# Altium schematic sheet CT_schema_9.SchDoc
size 254 x 194 mm
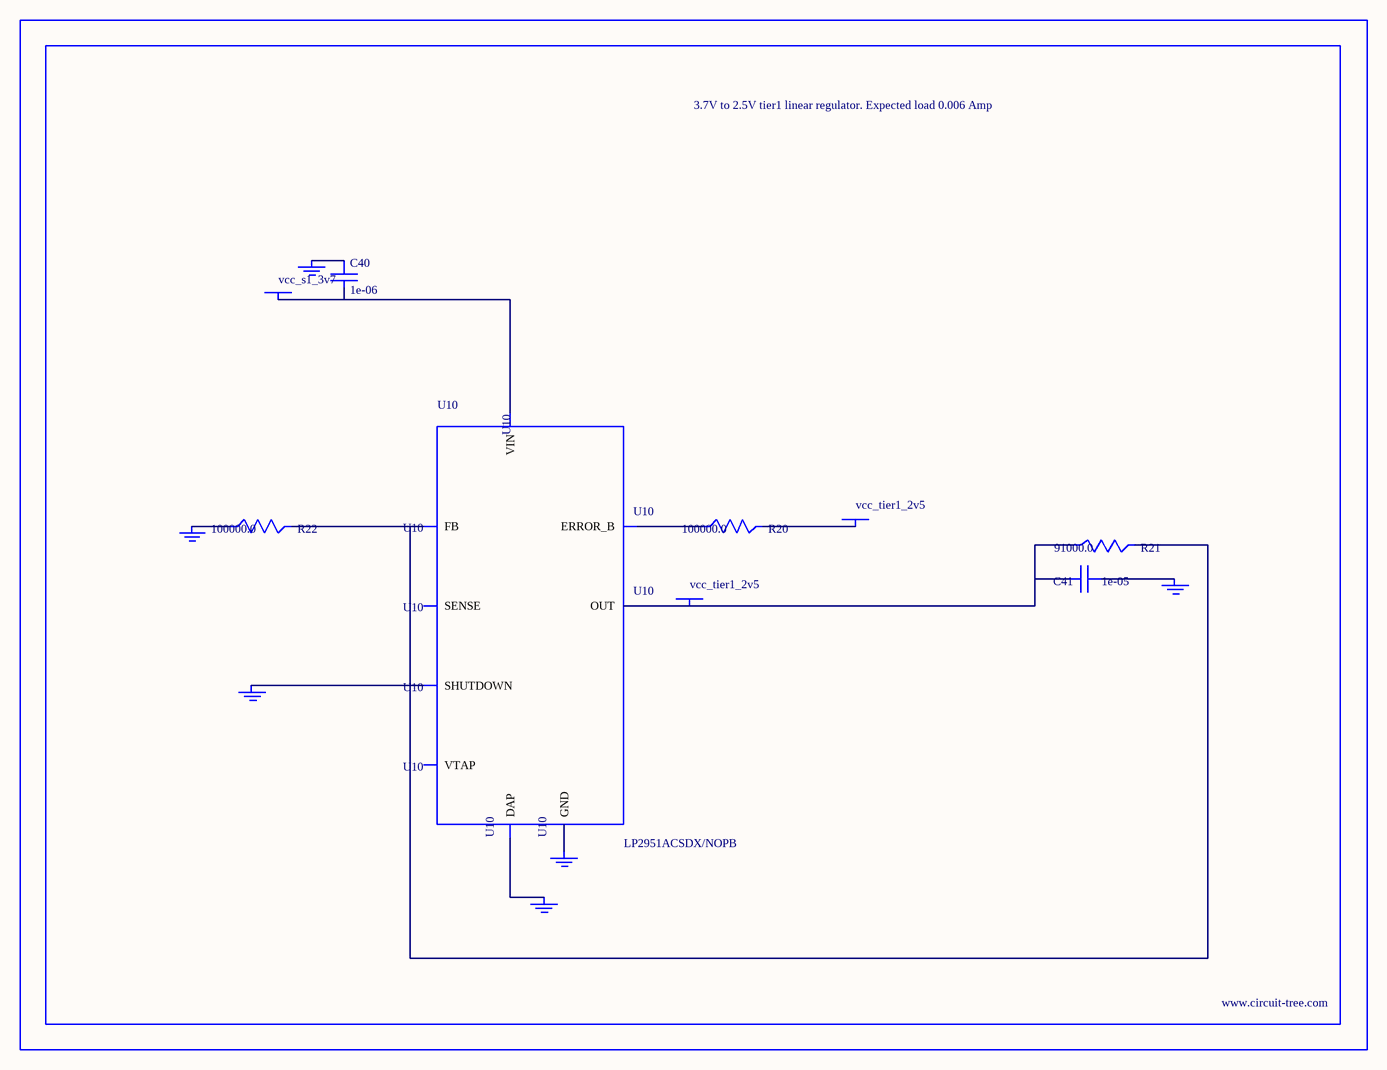
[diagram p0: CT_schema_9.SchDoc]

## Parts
BORDER8  (no value)
C40  1e-06  [C0603]
C41  1e-05  [C1210]
GND_INSTANCE_8_0  (no value)
GND_INSTANCE_8_1  (no value)
GND_INSTANCE_8_2  (no value)
GND_INSTANCE_8_3  (no value)
GND_INSTANCE_8_4  (no value)
GND_INSTANCE_8_5  (no value)
POWER_INSTANCE_8_0  vcc_tier1_2v5
POWER_INSTANCE_8_1  vcc_s1_3v7
POWER_INSTANCE_8_2  vcc_tier1_2v5
R20  100000.0  [R0603]
R21  91000.0  [R0603]
R22  100000.0  [R0603]
U10  LP2951ACSDX/NOPB  [WSON-8]

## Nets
NetC40_1: C40.1 GND_INSTANCE_8_3.0(GND)
NetC40_2: C40.2 POWER_INSTANCE_8_1.0(PWR) U10.8(VIN)
NetC41_1: C41.1 GND_INSTANCE_8_0.0(GND)
NetC41_2: C41.2 POWER_INSTANCE_8_2.0(PWR) R21.1 U10.1(OUT)
NetGND_INSTANCE_8_1_0: GND_INSTANCE_8_1.0(GND) U10.3(SHUTDOWN)
NetGND_INSTANCE_8_2_0: GND_INSTANCE_8_2.0(GND) R22.1
NetGND_INSTANCE_8_4_0: GND_INSTANCE_8_4.0(GND) U10.PAD(DAP)
NetGND_INSTANCE_8_5_0: GND_INSTANCE_8_5.0(GND) U10.4(GND)
NetPOWER_INSTANCE_8_0_0: POWER_INSTANCE_8_0.0(PWR) R20.2
NetR20_1: R20.1 U10.5(ERROR_B)
NetR21_2: R21.2 R22.2 U10.7(FB)

Not connected (* = marked no-connect by the designer): U10 2(SENSE) 6(VTAP)

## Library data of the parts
BORDER8 = BORDER_PAGE8
C40 = C0603C105K3RACTU
C41 = GRM32DR61E106MA12L
GND_INSTANCE_8_0-GND_INSTANCE_8_5 = GND
POWER_INSTANCE_8_0-POWER_INSTANCE_8_2 = PWR
R20 R22 = RC0603JR-07100KL
R21 = RC0603JR-0791KL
